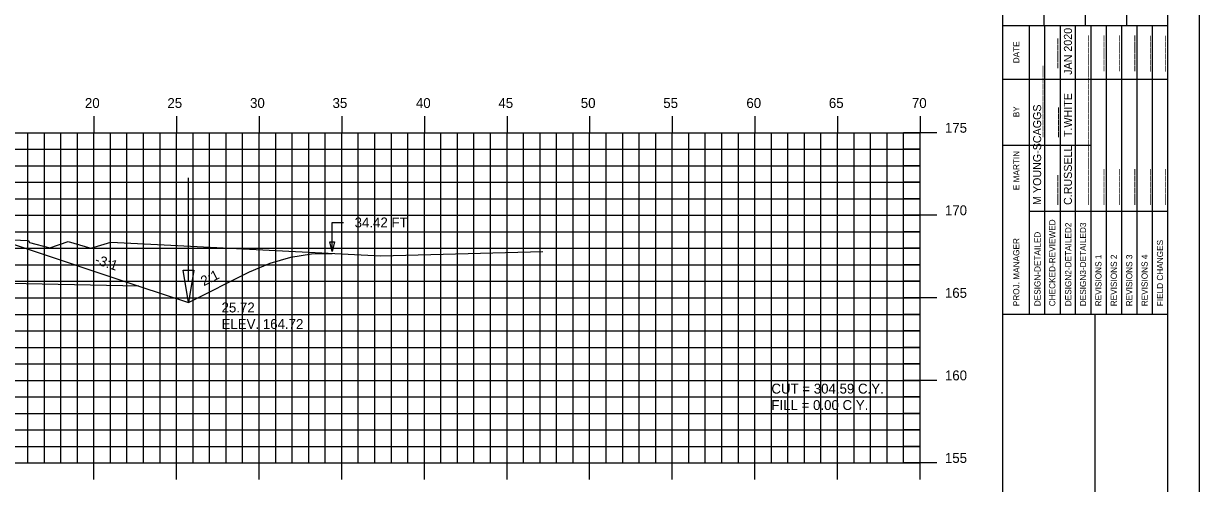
# Model space of a CAD drawing. Extents: x 1141868 to 1142038, y 608981 to 609091.
# Drawn here: x 1141966.5 to 1142037.7, y 609019.1 to 609047 of the extents above; entities that cross this region are included whole.
import ezdxf

# ---------------------------------------------------------------- set-up
doc = ezdxf.new("R2010")
doc.units = 0
for name, color, linetype in [('ANNOTATION', 7, 'Continuous'), ('BORDER', 7, 'Continuous'), ('D_Drainage_Ditch_Line', 7, 'Continuous'), ('D_Roadway_SlopeLines', 7, 'Continuous'), ('D_Roadway_SubGrade', 7, 'Continuous'), ('D_Text_Standard', 7, 'Continuous'), ('H_V ANNOTATION', 7, 'Continuous'), ('MAJOR', 7, 'Continuous'), ('MINOR', 7, 'Continuous'), ('PLOT BOUNDARY', 7, 'Continuous'), ('S_Roadway_Centerline', 7, 'Continuous')]:
    doc.layers.add(name, color=color, linetype=linetype)

msp = doc.modelspace()

# ---------------------------------------------------------------- linework, layer by layer
msp.add_lwpolyline([(1141914.753, 609033.917), (1141916.003, 609033.855), (1141917.253, 609033.633), (1141918.503, 609033.249), (1141919.753, 609032.704), (1141925.059, 609030.051), (1141928.059, 609031.051), (1141935.783, 609033.626), (1141935.784, 609033.626), (1141939.784, 609033.786), (1141950.784, 609034.006), (1141961.784, 609033.786), (1141965.784, 609033.626), (1141973.507, 609031.051), (1141976.507, 609030.051), (1141980.207, 609031.901), (1141981.457, 609032.44), (1141982.707, 609032.807), (1141983.957, 609033.002), (1141985.207, 609033.025)])
at = {"layer": 'BORDER'}
for p, q in [((1142025.784, 608984.335), (1142025.784, 609089.335)), ((1142028.284, 609046.838), (1142028.284, 609055.485)), ((1142030.784, 609046.838), (1142030.784, 609055.485)), ((1142033.284, 609046.838), (1142033.284, 609055.485)), ((1142025.784, 609046.838), (1142035.784, 609046.838)), ((1142025.784, 609029.338), (1142035.784, 609029.338)), ((1142031.375, 608994.338), (1142031.375, 609029.338))]:
    msp.add_line(p, q, dxfattribs=at)
msp.add_lwpolyline([(1141875.784, 608984.335), (1142035.784, 608984.335), (1142035.784, 609089.335), (1141875.784, 609089.335)], close=True, dxfattribs=at)
for points in [[(1142027.399, 609043.588), (1142027.399, 609046.838)], [(1142028.331, 609029.341), (1142028.331, 609046.838)], [(1142029.263, 609046.838), (1142029.263, 609029.341)], [(1142030.195, 609029.341), (1142030.195, 609046.838)], [(1142031.126, 609029.341), (1142031.126, 609046.838)], [(1142032.058, 609029.341), (1142032.058, 609046.838)], [(1142032.99, 609029.341), (1142032.99, 609046.838)], [(1142033.922, 609029.341), (1142033.922, 609046.838)], [(1142034.853, 609029.341), (1142034.853, 609046.838)], [(1142027.4, 609029.341), (1142027.4, 609046.132)], [(1142025.784, 609043.588), (1142035.784, 609043.588)], [(1142025.784, 609039.588), (1142027.4, 609039.588)], [(1142027.399, 609039.588), (1142031.126, 609039.588)], [(1142027.399, 609035.588), (1142035.784, 609035.588)]]:
    msp.add_lwpolyline(points, dxfattribs=at)
at = {"layer": 'D_Drainage_Ditch_Line'}
msp.add_line((1141976.507, 609031.363), (1141976.508, 609037.607), dxfattribs=at)
msp.add_lwpolyline([(1141976.179, 609032.02), (1141976.835, 609032.02), (1141976.507, 609030.051)], close=True, dxfattribs=at)
at = {"layer": 'D_Roadway_SlopeLines'}
for points in [[(1141976.507, 609030.051), (1141980.207, 609031.901), (1141981.457, 609032.44), (1141982.707, 609032.807), (1141983.957, 609033.002), (1141985.207, 609033.025)], [(1141973.507, 609031.051), (1141976.507, 609030.051)]]:
    msp.add_lwpolyline(points, dxfattribs=at)
at = {"layer": 'D_Roadway_SubGrade'}
msp.add_lwpolyline([(1141961.784, 609033.369), (1141961.784, 609033.536), (1141965.784, 609033.376), (1141965.784, 609033.626), (1141965.784, 609033.626), (1141973.507, 609031.051), (1141961.784, 609031.286)], close=True, dxfattribs=at)
at = {"layer": 'D_Text_Standard'}
msp.add_lwpolyline([(1141985.207, 609033.151), (1141985.201, 609034.9), (1141985.881, 609034.9)], dxfattribs=at)
msp.add_lwpolyline([(1141985.207, 609033.151), (1141985.059, 609033.733), (1141985.35, 609033.733)], close=True, dxfattribs=at)
at = {"layer": 'MAJOR'}
for p, q in [((1141970.784, 609041.337), (1141970.784, 609040.335)), ((1141975.784, 609041.337), (1141975.784, 609040.335)), ((1141980.784, 609041.337), (1141980.784, 609040.335)), ((1141985.784, 609041.337), (1141985.784, 609040.335)), ((1141990.784, 609041.337), (1141990.784, 609040.335)), ((1141995.784, 609041.337), (1141995.784, 609040.335)), ((1142000.784, 609041.337), (1142000.784, 609040.335)), ((1142005.784, 609041.337), (1142005.784, 609040.335)), ((1142010.784, 609041.337), (1142010.784, 609040.335)), ((1142015.784, 609041.337), (1142015.784, 609040.335)), ((1142020.784, 609041.337), (1142020.784, 609040.335)), ((1141880.784, 609040.335), (1142020.784, 609040.335)), ((1141880.784, 609040.335), (1142020.784, 609040.335)), ((1141970.784, 609020.335), (1141970.784, 609040.335)), ((1141975.784, 609020.335), (1141975.784, 609040.335)), ((1141980.784, 609020.335), (1141980.784, 609040.335)), ((1141985.784, 609020.335), (1141985.784, 609040.335)), ((1141990.784, 609020.335), (1141990.784, 609040.335)), ((1141995.784, 609020.335), (1141995.784, 609040.335)), ((1142000.784, 609020.335), (1142000.784, 609040.335)), ((1142005.784, 609020.335), (1142005.784, 609040.335)), ((1142010.784, 609020.335), (1142010.784, 609040.335)), ((1142015.784, 609020.335), (1142015.784, 609040.335)), ((1142021.786, 609040.335), (1142019.782, 609040.335)), ((1142020.784, 609020.335), (1142020.784, 609040.335)), ((1142020.784, 609020.335), (1142020.784, 609040.335)), ((1141880.784, 609035.335), (1142020.784, 609035.335)), ((1142021.786, 609035.335), (1142019.782, 609035.335)), ((1141880.784, 609030.335), (1142020.784, 609030.335)), ((1142021.786, 609030.335), (1142019.782, 609030.335)), ((1141880.784, 609025.335), (1142020.784, 609025.335)), ((1142021.786, 609025.335), (1142019.782, 609025.335)), ((1141880.784, 609020.335), (1142020.784, 609020.335)), ((1141880.784, 609020.335), (1142020.784, 609020.335)), ((1141970.784, 609019.333), (1141970.784, 609020.335)), ((1141975.784, 609019.333), (1141975.784, 609020.335)), ((1141980.784, 609019.333), (1141980.784, 609020.335)), ((1141985.784, 609019.333), (1141985.784, 609020.335)), ((1141990.784, 609019.333), (1141990.784, 609020.335)), ((1141995.784, 609019.333), (1141995.784, 609020.335)), ((1142000.784, 609019.333), (1142000.784, 609020.335)), ((1142005.784, 609019.333), (1142005.784, 609020.335)), ((1142010.784, 609019.333), (1142010.784, 609020.335)), ((1142015.784, 609019.333), (1142015.784, 609020.335)), ((1142021.786, 609020.335), (1142019.782, 609020.335)), ((1142020.784, 609019.333), (1142020.784, 609020.335))]:
    msp.add_line(p, q, dxfattribs=at)
at = {"layer": 'MINOR'}
for p, q in [((1141966.784, 609020.335), (1141966.784, 609040.335)), ((1141967.784, 609020.335), (1141967.784, 609040.335)), ((1141968.784, 609020.335), (1141968.784, 609040.335)), ((1141969.784, 609020.335), (1141969.784, 609040.335)), ((1141971.784, 609020.335), (1141971.784, 609040.335)), ((1141972.784, 609020.335), (1141972.784, 609040.335)), ((1141973.784, 609020.335), (1141973.784, 609040.335)), ((1141974.784, 609020.335), (1141974.784, 609040.335)), ((1141976.784, 609020.335), (1141976.784, 609040.335)), ((1141977.784, 609020.335), (1141977.784, 609040.335)), ((1141978.784, 609020.335), (1141978.784, 609040.335)), ((1141979.784, 609020.335), (1141979.784, 609040.335)), ((1141981.784, 609020.335), (1141981.784, 609040.335)), ((1141982.784, 609020.335), (1141982.784, 609040.335)), ((1141983.784, 609020.335), (1141983.784, 609040.335)), ((1141984.784, 609020.335), (1141984.784, 609040.335)), ((1141986.784, 609020.335), (1141986.784, 609040.335)), ((1141987.784, 609020.335), (1141987.784, 609040.335)), ((1141988.784, 609020.335), (1141988.784, 609040.335)), ((1141989.784, 609020.335), (1141989.784, 609040.335)), ((1141991.784, 609020.335), (1141991.784, 609040.335)), ((1141992.784, 609020.335), (1141992.784, 609040.335)), ((1141993.784, 609020.335), (1141993.784, 609040.335)), ((1141994.784, 609020.335), (1141994.784, 609040.335)), ((1141996.784, 609020.335), (1141996.784, 609040.335)), ((1141997.784, 609020.335), (1141997.784, 609040.335)), ((1141998.784, 609020.335), (1141998.784, 609040.335)), ((1141999.784, 609020.335), (1141999.784, 609040.335)), ((1142001.784, 609020.335), (1142001.784, 609040.335)), ((1142002.784, 609020.335), (1142002.784, 609040.335)), ((1142003.784, 609020.335), (1142003.784, 609040.335)), ((1142004.784, 609020.335), (1142004.784, 609040.335)), ((1142006.784, 609020.335), (1142006.784, 609040.335)), ((1142007.784, 609020.335), (1142007.784, 609040.335)), ((1142008.784, 609020.335), (1142008.784, 609040.335)), ((1142009.784, 609020.335), (1142009.784, 609040.335)), ((1142011.784, 609020.335), (1142011.784, 609040.335)), ((1142012.784, 609020.335), (1142012.784, 609040.335)), ((1142013.784, 609020.335), (1142013.784, 609040.335)), ((1142014.784, 609020.335), (1142014.784, 609040.335)), ((1142016.784, 609020.335), (1142016.784, 609040.335)), ((1142017.784, 609020.335), (1142017.784, 609040.335)), ((1142018.784, 609020.335), (1142018.784, 609040.335)), ((1142019.784, 609020.335), (1142019.784, 609040.335)), ((1141880.784, 609039.335), (1142020.784, 609039.335)), ((1142020.784, 609039.335), (1142019.782, 609039.335)), ((1141880.784, 609038.335), (1142020.784, 609038.335)), ((1142020.784, 609038.335), (1142019.782, 609038.335)), ((1141880.784, 609037.335), (1142020.784, 609037.335)), ((1142020.784, 609037.335), (1142019.782, 609037.335)), ((1141880.784, 609036.335), (1142020.784, 609036.335)), ((1142020.784, 609036.335), (1142019.782, 609036.335)), ((1141880.784, 609034.335), (1142020.784, 609034.335)), ((1142020.784, 609034.335), (1142019.782, 609034.335)), ((1141880.784, 609033.335), (1142020.784, 609033.335)), ((1142020.784, 609033.335), (1142019.782, 609033.335)), ((1141880.784, 609032.335), (1142020.784, 609032.335)), ((1142020.784, 609032.335), (1142019.782, 609032.335)), ((1141880.784, 609031.335), (1142020.784, 609031.335)), ((1142020.784, 609031.335), (1142019.782, 609031.335)), ((1141880.784, 609029.335), (1142020.784, 609029.335)), ((1142020.784, 609029.335), (1142019.782, 609029.335)), ((1141880.784, 609028.335), (1142020.784, 609028.335)), ((1142020.784, 609028.335), (1142019.782, 609028.335)), ((1141880.784, 609027.335), (1142020.784, 609027.335)), ((1142020.784, 609027.335), (1142019.782, 609027.335)), ((1141880.784, 609026.335), (1142020.784, 609026.335)), ((1142020.784, 609026.335), (1142019.782, 609026.335)), ((1141880.784, 609024.335), (1142020.784, 609024.335)), ((1142020.784, 609024.335), (1142019.782, 609024.335)), ((1141880.784, 609023.335), (1142020.784, 609023.335)), ((1142020.784, 609023.335), (1142019.782, 609023.335)), ((1141880.784, 609022.335), (1142020.784, 609022.335)), ((1142020.784, 609022.335), (1142019.782, 609022.335)), ((1141880.784, 609021.335), (1142020.784, 609021.335)), ((1142020.784, 609021.335), (1142019.782, 609021.335))]:
    msp.add_line(p, q, dxfattribs=at)
at = {"layer": 'PLOT BOUNDARY'}
msp.add_lwpolyline([(1141867.691, 608981.276), (1142037.691, 608981.276), (1142037.691, 609091.276), (1141867.691, 609091.276)], close=True, dxfattribs=at)
at = {"layer": 'S_Roadway_Centerline'}
msp.add_lwpolyline([(1141898.714, 609033.675), (1141917.629, 609033.96), (1141928.482, 609033.842), (1141932.036, 609032.906), (1141933.204, 609032.648), (1141934.418, 609032.95), (1141936.171, 609033.793), (1141938.888, 609033.718), (1141940.258, 609033.785), (1141943.4, 609033.889), (1141951.951, 609034.107), (1141958.412, 609033.998), (1141962.656, 609033.973), (1141964.386, 609033.91), (1141966.817, 609033.803), (1141966.877, 609033.693), (1141968.111, 609033.369), (1141969.228, 609033.74), (1141970.594, 609033.351), (1141971.805, 609033.711), (1141975.428, 609033.517), (1141988.146, 609032.877), (1141997.951, 609033.132)], dxfattribs=at)

# ---------------------------------------------------------------- texts
at = {"layer": 'ANNOTATION'}
for s, rotation, p in [('-3:1', 341.56521, (1141970.795, 609032.409)), ('2:1', 26.56505, (1141977.43, 609031.03))]:
    msp.add_text(s, height=0.6, rotation=rotation, dxfattribs=at).set_placement(p)
at = {"layer": 'BORDER'}
for s, height, p in [('JAN 2020', 0.4845, (1142029.97, 609043.843)), ('DATE', 0.3714, (1142026.788, 609044.544)), ('_____', 0.4845, (1142029.001, 609044.243)), ('______', 0.4845, (1142030.865, 609044.063)), ('______', 0.4845, (1142031.796, 609044.065)), ('______', 0.4845, (1142032.728, 609044.067)), ('______', 0.4845, (1142033.66, 609044.067)), ('______', 0.4845, (1142034.591, 609044.036)), ('______', 0.4845, (1142035.523, 609044.036)), ('____________', 0.48455, (1142028.107, 609040.073)), ('____________', 0.48455, (1142030.865, 609040.073)), ('T.WHITE', 0.4845, (1142029.97, 609040.073)), ('M YOUNG-SCAGGS', 0.48455, (1142028.107, 609035.961)), ('BY', 0.3714, (1142026.788, 609041.273)), ('_____', 0.4845, (1142029.039, 609040.073)), ('____________', 0.48455, (1142030.865, 609035.961)), ('E MARTIN', 0.3727, (1142026.788, 609036.855)), ('C.RUSSELL', 0.4845, (1142029.97, 609035.961)), ('_____', 0.4845, (1142029.001, 609035.961)), ('______', 0.4845, (1142031.796, 609035.961)), ('______', 0.4845, (1142032.728, 609035.961)), ('______', 0.4845, (1142033.66, 609035.961)), ('______', 0.4845, (1142034.591, 609035.961)), ('______', 0.4845, (1142035.523, 609035.961)), ('CHECKED-REVIEWED', 0.37275, (1142028.965, 609029.826)), ('DESIGN3-DETAILED3', 0.37275, (1142030.828, 609029.826)), ('DESIGN-DETAILED', 0.37275, (1142028.071, 609029.826)), ('DESIGN2-DETAILED2', 0.37275, (1142029.934, 609029.826)), ('PROJ. MANAGER', 0.37275, (1142026.788, 609029.826)), ('FIELD CHANGES', 0.37275, (1142035.487, 609029.826)), ('REVISIONS 1', 0.37275, (1142031.76, 609029.826)), ('REVISIONS 2', 0.37275, (1142032.692, 609029.826)), ('REVISIONS 3', 0.37275, (1142033.623, 609029.826)), ('REVISIONS 4', 0.37275, (1142034.555, 609029.826))]:
    msp.add_text(s, height=height, rotation=90, dxfattribs=at).set_placement(p)
at = {"layer": 'D_Text_Standard'}
for s, p in [('34.42 FT', (1141986.561, 609034.6)), ('25.72', (1141978.507, 609029.451)), ('ELEV. 164.72', (1141978.507, 609028.449)), ('CUT = 304.59 C.Y.', (1142011.784, 609024.535)), ('FILL = 0.00 C.Y.', (1142011.784, 609023.539))]:
    msp.add_text(s, height=0.6, dxfattribs=at).set_placement(p)
at = {"layer": 'H_V ANNOTATION'}
for s, p in [('20', (1141970.238, 609041.835)), ('25', (1141975.23, 609041.835)), ('30', (1141980.232, 609041.835)), ('35', (1141985.224, 609041.835)), ('40', (1141990.27, 609041.835)), ('45', (1141995.262, 609041.835)), ('50', (1142000.248, 609041.835)), ('55', (1142005.24, 609041.835)), ('60', (1142010.27, 609041.835)), ('65', (1142015.262, 609041.835)), ('70', (1142020.286, 609041.835)), ('175', (1142022.284, 609040.335)), ('170', (1142022.284, 609035.335)), ('165', (1142022.284, 609030.335)), ('160', (1142022.284, 609025.335)), ('155', (1142022.284, 609020.335))]:
    msp.add_text(s, height=0.6, dxfattribs=at).set_placement(p)

doc.saveas('drawing.dxf')
